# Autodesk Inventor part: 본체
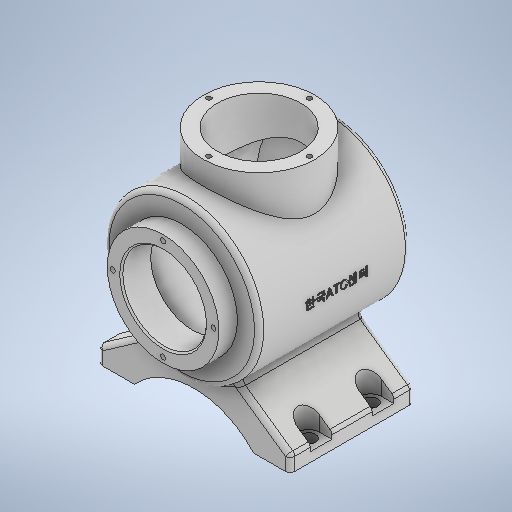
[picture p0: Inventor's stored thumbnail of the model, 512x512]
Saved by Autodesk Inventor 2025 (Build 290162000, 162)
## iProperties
Created: 2024-07
Part Number: 본체
Material: 일반
Document SubType Name: Modeling
Designer: hsj03
Density: 1 g/cm^3
Appearance: 기본값
Author: hsj03
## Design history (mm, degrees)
sketch "스케치9"
  geometry: C1 r 50 at (0, 0); 1 further point
  constraints: 1 centre point, 1 coincident
  dimensions: "d23" = 100 diameter of C1
extrude "돌출3" new body sketch "스케치9" stored distance "d24" = 108; taper "d25" = 0 deg
sketch "스케치10"
  geometry: L1 (-50, -54)-(50, -54) reference; L2 (50, 54)-(-50, 54) reference; L3 (50, -42.336)-(50, 54); L4 (50, 54)-(-7.913, 54); L5 (0, -54)-(0, 54); L6 (50, 54)-(0, 54); A1 r 113 centre (0, 59) between (0, -54) and (50, -42.336); 2 further points
  constraints: 8 end point, 2 midpoint, 2 point on circle, 2 point on line, 2 vertical, 1 centre point, 1 vertical alignment
  dimensions: "d26" = 226 diameter of A1
revolve "회전2" sketch "스케치10" stored, may be unused: angle "d27" = 360 deg
sketch "스케치11"
  geometry: C1 r 36 at (0, 0); 1 further point
  constraints: 1 centre point, 1 coincident
  dimensions: "d28" = 72 diameter of C1
extrude "돌출4" join sketch "스케치11" distance "d29" = 12; taper "d30" = 0 deg
fillet "모깎기1" dims "d31" = 3
feature "쉘1" dims "d32" = 7, "d99" = 9
node "작업 평면1"
sketch "스케치13"
  geometry: L1 (36, 66)-(-36, 66) reference; C1 r 36 at (0, 4); 1 further point
  constraints: 1 centre point
  dimensions: "d100" = 62 distance from line of L1 C1.centre; "d101" = 72 diameter of C1
extrude "돌출5" join sketch "스케치13" stored distance "d35" = 12; taper "d36" = 0 deg
node "작업 평면2"
sketch "스케치14"
  geometry: L1 (-26.694, -42.278)-(-62, -67); L2 (-62, -67)-(-62, -77); L3 (-62, -77)-(-38.5, -77); L4 (26.694, -42.278)-(62, -67); L5 (62, -67)-(62, -77); L6 (62, -77)-(38.5, -77); L7 (0, 25.398)-(0, -122.418); L8 (-26.694, -42.278)-(26.556, -42.365); A1 r 50 centre (0, 0) between (-26.694, -42.278) and (26.694, -42.278) reference; A2 r 52.096 centre (0, -112.096) between (38.5, -77) and (-38.5, -77); 2 further points
  constraints: 16 end point, 6 point on circle, 3 vertical, 2 perpendicular, 2 point on line, 1 centre point, 1 midpoint, 3 other
  dimensions: "d38" = 10 distance of L4.end L5.end; "d39" = 17 vertical distance of L6.end point (0, -60); "d40" = 77 distance of L3.end L6.end; "d41" = 77 vertical distance of point (50.25, -77) A1.centre; "d42" = 55 deg angle of L5 L4; "d43" = 124 distance between parallel lines of L5 L2
extrude "돌출6" join sketch "스케치14" distance "d44" = 80; taper "d45" = 0 deg
sketch "스케치15"
  geometry: C1 r 36 at (0, 0) reference; 1 further point
  constraints: 1 coincident
hole "구멍1" sketch "스케치15" at (0, 0) diameter "d46" = 54; stored, may be unused: countersink angle "d50" = 90 deg, drill point angle "d52" = 0 deg; dims "d47" = 6, "d48" = 4, "d49" = 2, "d51" = 50
node "작업 평면3"
sketch "스케치16" dims "d54" = 14
  geometry: L1 (-38.5, -100.641)-(-38.5, 25.831); L2 (-111.678, -40)-(58.457, -40); L3 (23.5, 0)-(23.5, -80) reference; L4 (-100.5, -67)-(-92.5, -67); L5 (-92.5, -67)-(-92.5, -53); L6 (-92.5, -53)-(-100.5, -53); L7 (-100.5, -53)-(-100.5, -67); L8 (-100.5, -67)-(-92.5, -53); L9 (-92.5, -67)-(-100.5, -53); L10 (-100.5, 0)-(-100.5, -80) reference; L11 (-100.5, -27)-(-92.5, -27); L12 (-92.5, -27)-(-92.5, -13); L13 (-92.5, -13)-(-100.5, -13); L14 (-100.5, -13)-(-100.5, -27); L15 (-100.5, -27)-(-92.5, -13); L16 (-92.5, -27)-(-100.5, -13); L17 (15.5, -67)-(23.5, -67); L18 (23.5, -67)-(23.5, -53); L19 (23.5, -53)-(15.5, -53); L20 (15.5, -53)-(15.5, -67); L21 (15.5, -67)-(23.5, -53); L22 (23.5, -67)-(15.5, -53); L23 (15.5, -27)-(23.5, -27); L24 (23.5, -27)-(23.5, -13); L25 (23.5, -13)-(15.5, -13); L26 (15.5, -13)-(15.5, -27); L27 (15.5, -27)-(23.5, -13); L28 (23.5, -27)-(15.5, -13); 22 further points
  constraints: 52 end point, 13 midpoint, 8 parallel, 5 horizontal, 4 coincident, 4 perpendicular, 4 symmetric about line, 3 collinear, 2 point on line, 1 vertical, 12 other
  dimensions: "d55" = 40 distance of point (15.5, -20) point (15.5, -60); "d56" = 8 distance from line of L3 point (15.5, -60)
extrude "돌출7" cut sketch "스케치16" distance "d57" = 50; taper "d58" = 0 deg
sketch "스케치17" dims "d66" = 65
  geometry: C1 r 36 at (0, 0) reference; 2 further points
  constraints: 2 vertical alignment, 1 coincident, 2 other
hole "구멍2" sketch "스케치17" at (0, 32.5) diameter "d59" = 3.242; stored, may be unused: countersink angle "d63" = 90 deg, drill point angle "d65" = 120 deg; dims "d60" = 8, "d61" = 4, "d62" = 2, "d64" = 10
sketch "스케치18" dims "d77" = 65
  geometry: C1 r 27 at (0, 0) reference; C2 r 36 at (0, 0) reference; 3 further points
  constraints: 1 coincident, 1 vertical alignment, 2 other
hole "구멍3" sketch "스케치18" at (0, -32.5) diameter "d70" = 3.242; stored, may be unused: countersink angle "d74" = 90 deg, drill point angle "d76" = 120 deg; dims "d71" = 8, "d72" = 4, "d73" = 2, "d75" = 10
sketch "스케치19"
  geometry: A1 r 7 centre (-92.5, 20) between (-92.5, 13) and (-92.5, 27) reference; A2 r 7 centre (-92.5, 60) between (-92.5, 53) and (-92.5, 67) reference; A3 r 7 centre (15.5, 60) between (15.5, 67) and (15.5, 53) reference; A4 r 7 centre (15.5, 20) between (15.5, 27) and (15.5, 13) reference; 4 further points
  constraints: 4 coincident
hole "구멍4" sketch "스케치19" at (-92.5, 20), (-92.5, 60), (15.5, 60), (15.5, 20) diameter "d81" = 9; stored, may be unused: countersink angle "d85" = 90 deg, drill point angle "d87" = 0 deg; dims "d82" = 8, "d83" = 4, "d84" = 2, "d86" = 10
fillet "모깎기5" dims "d91" = 3
fillet "모깎기4" dims "d90" = 3
fillet "모깎기2" dims "d88" = 3
chamfer "모따기1" distance "d92" = 1; stored, may be unused: second distance "d93" = 2, angle "d94" = 45 deg
node "작업 평면4"
sketch "스케치20"
  geometry: L1 (36, 66)-(-36, 66) reference; 2 further points
  constraints: 1 vertical alignment, 1 other
  dimensions: "d96" = 62 distance from line of L1 point (0, 4)
feature "엠보싱1" sketch "스케치20" dims "d97" = 0.5, "d98" = 0
node "솔리드4"
pattern_circular "원형 패턴1" dims angle "d68" = 360 deg
pattern_circular "원형 패턴2" dims angle "d79" = 360 deg
node "투영된 루프1"
node "투영된 루프2"
feature "A9D066F2-1C7D-4E18-AEED-F7BC21143FA4" dims "d46" = 54, "d47" = 6, "d48" = 4, "d49" = 2, "d50" = 90 deg, "d51" = 50, "d52" = 0
other parameters: "d17" = 226, "d33" = 65, "d53" = -6, "d95" = 116.5
